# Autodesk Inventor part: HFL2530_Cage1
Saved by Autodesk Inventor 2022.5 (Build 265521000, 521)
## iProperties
Created: 2024-12
Part Number: HFL2530_Cage1
Material: Generic
Document SubType Name: Modeling
Designer: AdminForWorker
Density: 1 g/cm^3
Appearance: Default
Title: HFL2530_Cage1
Author: AdminForWorker
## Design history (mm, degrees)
feature "Body1"
body "Solid1"
